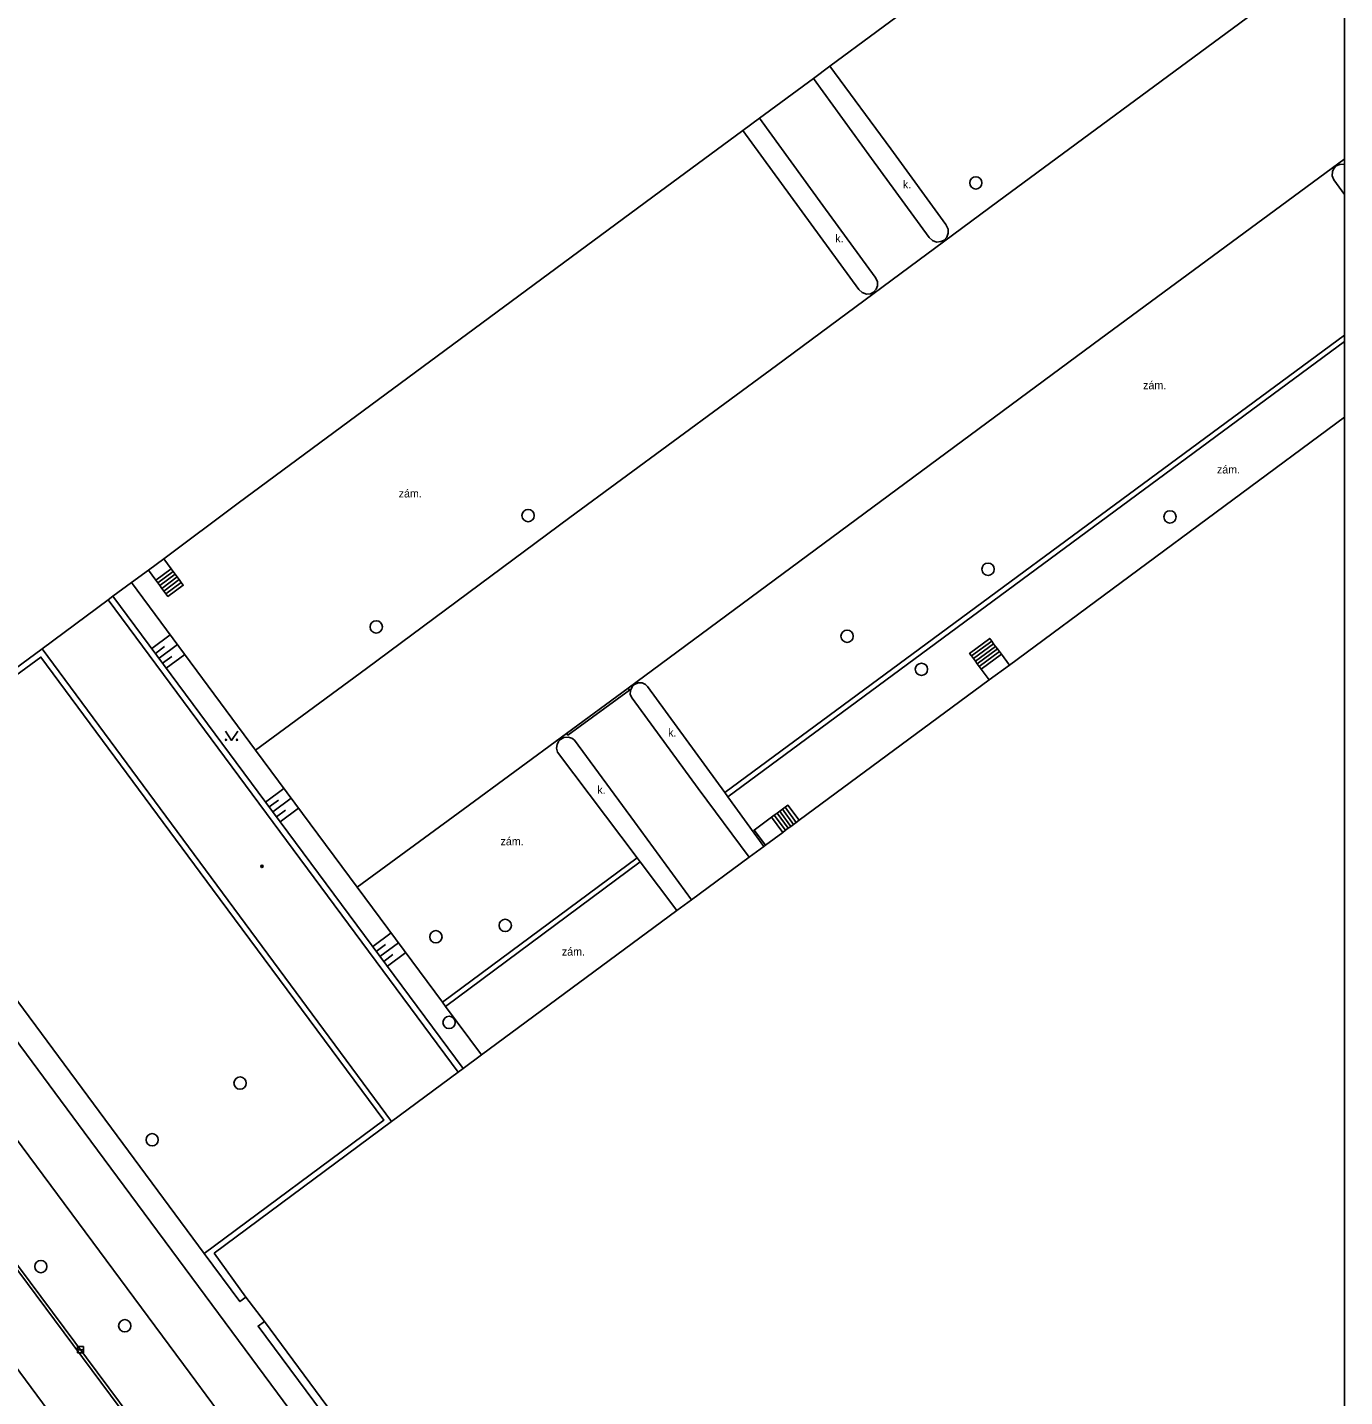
# Model space of a CAD drawing. Extents: x -596024 to -594475, y -1163820 to -1161957.
# Drawn here: x -594582.7 to -594475.5, y -1163179.9 to -1163068.4 of the extents above; entities that cross this region are included whole.
import ezdxf

# ---------------------------------------------------------------- set-up
doc = ezdxf.new("R2010")
doc.units = 0
for name, color, linetype in [('Level 10', 7, 'Continuous'), ('Level 11', 7, 'Continuous'), ('Level 14', 7, 'Continuous'), ('Level 15', 7, 'Continuous'), ('Level 24', 7, 'Continuous'), ('Level 27', 7, 'Continuous'), ('Level 36', 7, 'Continuous'), ('Level 39', 7, 'Continuous'), ('Level 40', 7, 'Continuous'), ('Level 5', 7, 'Continuous'), ('Level 51', 7, 'Continuous'), ('Vrstva 63', 7, 'Continuous')]:
    doc.layers.add(name, color=color, linetype=linetype)

msp = doc.modelspace()

# ---------------------------------------------------------------- linework, layer by layer
at = {"layer": 'Level 10'}
msp.add_line((-594475.47, -1163079.11), (-594475.53, -1163079.15), dxfattribs=at)
for points in [[(-594475.47, -1163061.74), (-594483.99, -1163068.06), (-594503.72, -1163082.61), (-594521.71, -1163095.93), (-594538.51, -1163108.29), (-594555.07, -1163120.58), (-594564.11, -1163127.23)], [(-594476.38, -1163295.95), (-594483.21, -1163286.71), (-594496.95, -1163267.99), (-594509.44, -1163251.06), (-594520.92, -1163235.64), (-594534.84, -1163216.72), (-594549.23, -1163197.24), (-594565.49, -1163175.29), (-594578.05, -1163158.33), (-594594.16, -1163136.56), (-594607.21, -1163118.84), (-594619.14, -1163102.72), (-594629.15, -1163089.16), (-594640.89, -1163073.35), (-594644.69, -1163076.23)], [(-594475.53, -1163079.15), (-594495.32, -1163093.74), (-594533.78, -1163122.18)], [(-594533.78, -1163122.18), (-594538.8, -1163125.87)], [(-594538.8, -1163125.87), (-594547.19, -1163132.08), (-594555.82, -1163138.4)], [(-594555.82, -1163138.4), (-594564.11, -1163127.23)]]:
    msp.add_lwpolyline(points, dxfattribs=at)
at = {"layer": 'Level 11'}
for points in [[(-594658.25, -1163068.41), (-594648.78, -1163081.26), (-594637.52, -1163096.5), (-594627.94, -1163109.39), (-594616.36, -1163125.13), (-594603.5, -1163142.69), (-594587.25, -1163164.52), (-594574.42, -1163181.74), (-594559, -1163202.7), (-594543.73, -1163223.28), (-594530.41, -1163241.31), (-594518.2, -1163257.82), (-594506.57, -1163273.57), (-594492.81, -1163292.25), (-594492.53, -1163292.63), (-594483.61, -1163304.74), (-594481.85, -1163307.13)], [(-594657.91, -1163068.45), (-594648.58, -1163081.11), (-594637.31, -1163096.34), (-594627.74, -1163109.24), (-594616.16, -1163124.98), (-594603.29, -1163142.54), (-594587.04, -1163164.37), (-594574.22, -1163181.58), (-594558.79, -1163202.55), (-594543.52, -1163223.13), (-594530.21, -1163241.16), (-594518, -1163257.67), (-594506.37, -1163273.42), (-594492.33, -1163292.48), (-594481.65, -1163306.98), (-594481.85, -1163307.13)], [(-594496.66, -1163295.08), (-594662.09, -1163071.26)], [(-594513.98, -1163079.07), (-594518.69, -1163072.56)], [(-594517.35, -1163071.56), (-594512.4, -1163078.3), (-594507.91, -1163084.46)], [(-594523.09, -1163075.8), (-594517.94, -1163082.91), (-594513.67, -1163088.75), (-594513.49, -1163089.08), (-594513.47, -1163089.44), (-594513.58, -1163089.73), (-594513.8, -1163089.97), (-594514.06, -1163090.1), (-594514.38, -1163090.13), (-594514.74, -1163090), (-594514.99, -1163089.75), (-594524.43, -1163076.8)], [(-594480.26, -1163298.73), (-594487.23, -1163289.32), (-594500.98, -1163270.61), (-594513.05, -1163254.27), (-594524.82, -1163238.32), (-594538.75, -1163219.51), (-594553.56, -1163199.46), (-594569.42, -1163177.97), (-594581.93, -1163161.1), (-594598.22, -1163139.15), (-594611.25, -1163121.45), (-594623.1, -1163105.4), (-594630.38, -1163095.55), (-594644.69, -1163076.23)], [(-594509.27, -1163085.52), (-594513.98, -1163079.07)], [(-594475.47, -1163079.57), (-594475.53, -1163079.55), (-594475.86, -1163079.56), (-594476.15, -1163079.69), (-594476.34, -1163079.89), (-594476.46, -1163080.15), (-594476.48, -1163080.48), (-594476.35, -1163080.82), (-594475.47, -1163082.01)], [(-594507.91, -1163084.46), (-594507.73, -1163084.83)], [(-594507.73, -1163084.83), (-594507.72, -1163085.16)], [(-594509.02, -1163085.76), (-594509.27, -1163085.52)], [(-594508.67, -1163085.88), (-594509.02, -1163085.76)], [(-594508.33, -1163085.85), (-594508.67, -1163085.88)], [(-594508.06, -1163085.72), (-594508.33, -1163085.85)], [(-594507.85, -1163085.49), (-594508.06, -1163085.72)], [(-594507.72, -1163085.16), (-594507.85, -1163085.49)], [(-594572.21, -1163113.4), (-594572.82, -1163112.58)], [(-594572.21, -1163113.4), (-594570.96, -1163112.48)], [(-594572.05, -1163113.62), (-594570.8, -1163112.7)], [(-594571.57, -1163111.66), (-594570.96, -1163112.48)], [(-594570.96, -1163112.48), (-594570.8, -1163112.7)], [(-594570.8, -1163112.7), (-594570.63, -1163112.92)], [(-594572.05, -1163113.62), (-594572.21, -1163113.4)], [(-594571.88, -1163113.85), (-594572.05, -1163113.62)], [(-594571.88, -1163113.85), (-594570.63, -1163112.92)], [(-594571.72, -1163114.07), (-594570.47, -1163113.14)], [(-594571.56, -1163114.29), (-594570.31, -1163113.36)], [(-594570.14, -1163113.59), (-594569.98, -1163113.81), (-594571.23, -1163114.73), (-594571.56, -1163114.29)], [(-594571.39, -1163114.51), (-594570.14, -1163113.59)], [(-594570.63, -1163112.92), (-594570.47, -1163113.14)], [(-594570.47, -1163113.14), (-594570.31, -1163113.36)], [(-594570.31, -1163113.36), (-594570.14, -1163113.59)], [(-594571.72, -1163114.07), (-594571.88, -1163113.85)], [(-594571.56, -1163114.29), (-594571.72, -1163114.07)], [(-594504.19, -1163118.36), (-594504.35, -1163118.15), (-594505.99, -1163119.36), (-594505.83, -1163119.57)], [(-594504.19, -1163118.36), (-594505.83, -1163119.57)], [(-594504.03, -1163118.58), (-594505.67, -1163119.78)], [(-594503.88, -1163118.79), (-594505.51, -1163120)], [(-594503.72, -1163119), (-594505.36, -1163120.21)], [(-594503.56, -1163119.21), (-594505.2, -1163120.42)], [(-594504.03, -1163118.58), (-594504.19, -1163118.36)], [(-594503.88, -1163118.79), (-594504.03, -1163118.58)], [(-594503.72, -1163119), (-594503.88, -1163118.79)], [(-594503.56, -1163119.21), (-594503.72, -1163119)], [(-594503.4, -1163119.43), (-594503.56, -1163119.21)], [(-594568.28, -1163168.21), (-594553.67, -1163157.36), (-594567.59, -1163138.54), (-594581.56, -1163119.66), (-594596.24, -1163130.41)], [(-594505.83, -1163119.57), (-594505.67, -1163119.78)], [(-594505.67, -1163119.78), (-594505.51, -1163120)], [(-594505.51, -1163120), (-594505.36, -1163120.21)], [(-594505.36, -1163120.21), (-594505.2, -1163120.42)], [(-594505.2, -1163120.42), (-594505.04, -1163120.64)], [(-594502.75, -1163120.31), (-594503.4, -1163119.43)], [(-594505.04, -1163120.64), (-594504.39, -1163121.51)], [(-594525.92, -1163130.69), (-594532.19, -1163122.06), (-594532.37, -1163121.89), (-594532.64, -1163121.77), (-594532.97, -1163121.76), (-594533.27, -1163121.89), (-594533.46, -1163122.08), (-594533.59, -1163122.37), (-594533.6, -1163122.71), (-594533.46, -1163123.01), (-594528.08, -1163130.37), (-594523.92, -1163135.95)], [(-594528.62, -1163139.42), (-594533.25, -1163133.07), (-594538.14, -1163126.43), (-594538.36, -1163126.27), (-594538.66, -1163126.19), (-594539, -1163126.22), (-594539.28, -1163126.37), (-594539.44, -1163126.54), (-594539.56, -1163126.77), (-594539.61, -1163127.09), (-594539.53, -1163127.4), (-594533.05, -1163136.01)], [(-594568.28, -1163168.21), (-594596.24, -1163130.41)], [(-594525.67, -1163131.03), (-594525.92, -1163130.69)], [(-594522.74, -1163135.08), (-594525.67, -1163131.03)], [(-594522.61, -1163134.98), (-594523.53, -1163133.74), (-594522.11, -1163132.7)], [(-594522.11, -1163132.7), (-594521.88, -1163132.53)], [(-594521.88, -1163132.53), (-594521.66, -1163132.36)], [(-594521.88, -1163132.53), (-594520.97, -1163133.76)], [(-594521.66, -1163132.36), (-594521.44, -1163132.2)], [(-594521.66, -1163132.36), (-594520.75, -1163133.6)], [(-594521.44, -1163132.2), (-594521.22, -1163132.04)], [(-594521.44, -1163132.2), (-594521.31, -1163132.37)], [(-594521.31, -1163132.37), (-594520.53, -1163133.44)], [(-594521.22, -1163132.04), (-594521, -1163131.88)], [(-594521.22, -1163132.04), (-594520.31, -1163133.28)], [(-594521, -1163131.88), (-594520.78, -1163131.72), (-594519.87, -1163132.95)], [(-594521, -1163131.88), (-594520.09, -1163133.12)], [(-594533.05, -1163136.01), (-594532.79, -1163136.34)], [(-594532.79, -1163136.34), (-594529.81, -1163140.3)], [(-594564.89, -1163171.75), (-594565.37, -1163172.12), (-594568.28, -1163168.21)], [(-594547.15, -1163195.69), (-594547.63, -1163196.01), (-594563.89, -1163174.11), (-594563.36, -1163173.74)]]:
    msp.add_lwpolyline(points, dxfattribs=at)
at = {"layer": 'Level 14'}
for points in [[(-594574.18, -1163113.59), (-594564.11, -1163127.23)], [(-594547.2, -1163153.15), (-594562.09, -1163133.07), (-594575.7, -1163114.71)], [(-594555.82, -1163138.4), (-594548.89, -1163147.75)], [(-594548.89, -1163147.75), (-594548.64, -1163148.09)], [(-594548.64, -1163148.09), (-594545.7, -1163152.04)]]:
    msp.add_lwpolyline(points, dxfattribs=at)
at = {"layer": 'Level 15'}
for points in [[(-594571.04, -1163117.84), (-594572.55, -1163118.96)], [(-594571.5, -1163118.8), (-594572.25, -1163119.36)], [(-594570.45, -1163118.65), (-594571.95, -1163119.76)], [(-594570.9, -1163119.61), (-594571.66, -1163120.16)], [(-594569.85, -1163119.45), (-594571.36, -1163120.57)], [(-594561.79, -1163130.35), (-594563.28, -1163131.46)], [(-594562.24, -1163131.31), (-594562.99, -1163131.86)], [(-594561.2, -1163131.16), (-594562.69, -1163132.26)], [(-594561.65, -1163132.11), (-594562.39, -1163132.66)], [(-594560.6, -1163131.96), (-594562.09, -1163133.07)], [(-594554.56, -1163143.22), (-594553.07, -1163142.11)], [(-594554.27, -1163143.63), (-594553.52, -1163143.07)], [(-594553.97, -1163144.03), (-594552.47, -1163142.92)], [(-594553.67, -1163144.43), (-594552.92, -1163143.87)], [(-594553.37, -1163144.83), (-594551.88, -1163143.72)]]:
    msp.add_lwpolyline(points, dxfattribs=at)
at = {"layer": 'Level 24'}
for p, q in [((-594475.53, -1163079.15), (-594475.47, -1163079.23)), ((-594525.92, -1163130.69), (-594475.47, -1163093.45)), ((-594475.47, -1163093.98), (-594525.67, -1163131.03))]:
    msp.add_line(p, q, dxfattribs=at)
for points in [[(-594533.78, -1163122.18), (-594533.66, -1163122.35), (-594538.68, -1163126.03), (-594538.8, -1163125.87)], [(-594548.89, -1163147.75), (-594533.05, -1163136.01)], [(-594532.79, -1163136.34), (-594548.64, -1163148.09)]]:
    msp.add_lwpolyline(points, dxfattribs=at)
at = {"layer": 'Level 27'}
msp.add_line((-594578.6, -1163176.04), (-594578.1, -1163176.04), dxfattribs=at)
msp.add_lwpolyline([(-594578.6, -1163176.29), (-594578.1, -1163176.29), (-594578.1, -1163175.79), (-594578.6, -1163175.79)], close=True, dxfattribs=at)
for centre in [(-594505.48, -1163081.07), (-594541.92, -1163108.15), (-594489.68, -1163108.26), (-594504.49, -1163112.52), (-594554.27, -1163117.21), (-594515.96, -1163117.97), (-594509.91, -1163120.66), (-594543.78, -1163141.5), (-594549.42, -1163142.43), (-594548.35, -1163149.4), (-594565.36, -1163154.34), (-594572.51, -1163158.95), (-594581.57, -1163169.27), (-594574.74, -1163174.09)]:
    msp.add_circle(centre, 0.5, dxfattribs=at)
at = {"layer": 'Level 36'}
msp.add_lwpolyline([(-594566.55, -1163125.7), (-594566.05, -1163126.45), (-594565.55, -1163125.7)], dxfattribs=at)
for centre in [(-594566.5, -1163126.4), (-594565.6, -1163126.4)]:
    msp.add_circle(centre, 0.05, dxfattribs=at)
at = {"layer": 'Level 39'}
for radius in [0.09, 0.0398]:
    msp.add_circle((-594563.58, -1163136.7), radius, dxfattribs=at)
at = {"layer": 'Level 5'}
msp.add_line((-594475.47, -1163100.14), (-594502.75, -1163120.31), dxfattribs=at)
for points in [[(-594502.07, -1163060.26), (-594517.35, -1163071.56)], [(-594518.69, -1163072.56), (-594523.09, -1163075.8)], [(-594517.35, -1163071.56), (-594518.69, -1163072.56)], [(-594523.09, -1163075.8), (-594524.43, -1163076.8)], [(-594524.43, -1163076.8), (-594531.76, -1163082.21)], [(-594531.76, -1163082.21), (-594548.69, -1163094.72)], [(-594548.69, -1163094.72), (-594565.52, -1163107.14)], [(-594565.52, -1163107.14), (-594571.57, -1163111.66)], [(-594572.82, -1163112.58), (-594574.18, -1163113.59)], [(-594571.57, -1163111.66), (-594572.82, -1163112.58)], [(-594574.18, -1163113.59), (-594575.7, -1163114.71)], [(-594575.7, -1163114.71), (-594576.09, -1163115)], [(-594581.46, -1163119), (-594576.09, -1163115)], [(-594547.6, -1163153.45), (-594576.09, -1163115)], [(-594581.46, -1163119), (-594595.97, -1163129.67)], [(-594553.04, -1163157.46), (-594581.46, -1163119)], [(-594502.75, -1163120.31), (-594504.39, -1163121.51)], [(-594504.39, -1163121.51), (-594519.87, -1163132.95)], [(-594520.97, -1163133.76), (-594521.19, -1163133.93)], [(-594520.75, -1163133.6), (-594520.97, -1163133.76)], [(-594520.53, -1163133.44), (-594520.75, -1163133.6)], [(-594520.31, -1163133.28), (-594520.53, -1163133.44)], [(-594520.09, -1163133.12), (-594520.31, -1163133.28)], [(-594519.87, -1163132.95), (-594520.09, -1163133.12)], [(-594522.61, -1163134.98), (-594522.74, -1163135.08)], [(-594521.19, -1163133.93), (-594522.61, -1163134.98)], [(-594523.92, -1163135.95), (-594528.62, -1163139.42)], [(-594522.74, -1163135.08), (-594523.92, -1163135.95)], [(-594528.62, -1163139.42), (-594529.81, -1163140.3)], [(-594529.81, -1163140.3), (-594545.7, -1163152.04)], [(-594545.7, -1163152.04), (-594547.2, -1163153.15)], [(-594553.04, -1163157.46), (-594547.6, -1163153.45)], [(-594547.2, -1163153.15), (-594547.6, -1163153.45)], [(-594567.47, -1163168.18), (-594553.04, -1163157.46)], [(-594564.89, -1163171.75), (-594567.47, -1163168.18)], [(-594563.36, -1163173.74), (-594564.89, -1163171.75)], [(-594547.15, -1163195.69), (-594563.36, -1163173.74)]]:
    msp.add_lwpolyline(points, dxfattribs=at)
at = {"layer": 'Level 51'}
for points in [[(-594503.4, -1163119.43), (-594505.04, -1163120.64)], [(-594522.11, -1163132.7), (-594521.19, -1163133.93)]]:
    msp.add_lwpolyline(points, dxfattribs=at)
at = {"layer": 'Vrstva 63'}
msp.add_lwpolyline([(-594475.47, -1163820.23), (-596024.42, -1163820.23), (-596024.42, -1161956.88), (-594475.47, -1161956.88)], close=True, dxfattribs=at)

# ---------------------------------------------------------------- texts
at = {"layer": 'Level 40'}
for s, p in [('k. ', (-594511.42, -1163081.51)), ('k. ', (-594516.92, -1163085.91)), ('zám.', (-594491.87, -1163097.86)), ('zám.', (-594485.86, -1163104.72)), ('zám.', (-594552.45, -1163106.67)), ('k. ', (-594530.52, -1163126.13)), ('k. ', (-594536.28, -1163130.79)), ('zám.', (-594544.16, -1163134.98)), ('zám.', (-594539.17, -1163143.96))]:
    msp.add_text(s, height=0.65, dxfattribs=at).set_placement(p)

doc.saveas('drawing.dxf')
